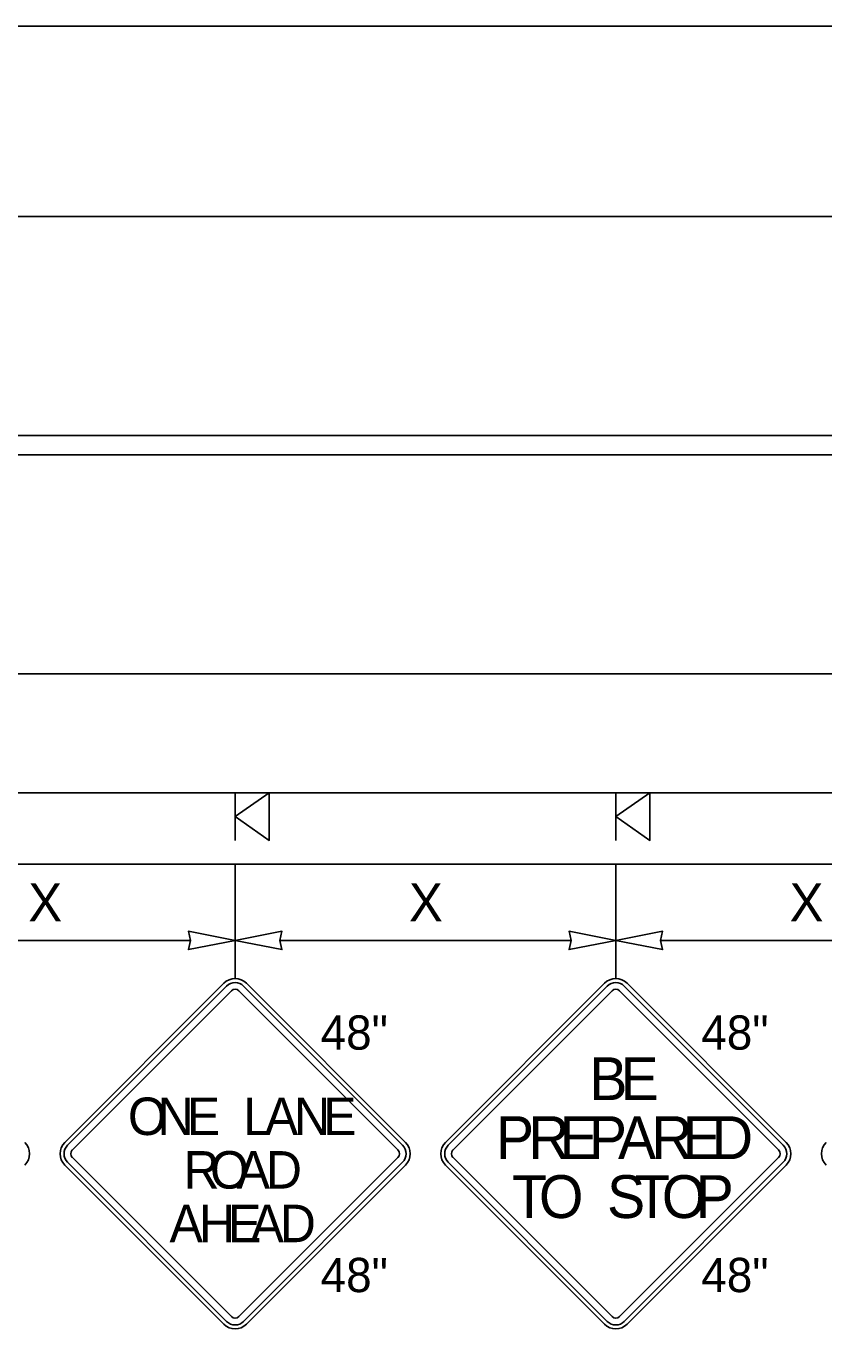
# Model space of a CAD drawing. Extents: x 99999.1 to 100095.7, y 99995 to 100010.7.
# Drawn here: x 100001.437 to 100003.114, y 100004.757 to 100007.492 of the extents above; entities that cross this region are included whole.
import ezdxf

# ---------------------------------------------------------------- set-up
doc = ezdxf.new("R2010")
doc.units = 0
for name, color, linetype in [('RD_ED_ShoulderPavedEdge', 7, 'Continuous'), ('RD_MK_LineDblYellowCenter', 7, 'Continuous'), ('RD_MK_LineEdgeWhite', 7, 'Continuous'), ('TR_SN_ConstructionSigns', 7, 'Continuous'), ('TR_WZ_PortableSignMountBlk-Org', 7, 'Continuous'), ('TR_WZ_WorkZoneDetails', 7, 'Continuous'), ('TR_WZ_WorkZoneTextCurrent', 7, 'Continuous')]:
    doc.layers.add(name, color=color, linetype=linetype)

msp = doc.modelspace()

# ---------------------------------------------------------------- linework, layer by layer
at = {"layer": 'RD_ED_ShoulderPavedEdge'}
for p, q in [((100000.1076, 100007.4923), (100015.6424, 100007.4923)), ((100000.1076, 100005.7323), (100015.6424, 100005.7323))]:
    msp.add_line(p, q, dxfattribs=at)
at = {"layer": 'RD_MK_LineDblYellowCenter'}
for p, q in [((100000.1282, 100006.6323), (100003.4767, 100006.6323)), ((100000.0869, 100006.5923), (100003.4767, 100006.5923))]:
    msp.add_line(p, q, dxfattribs=at)
at = {"layer": 'RD_MK_LineEdgeWhite'}
for p, q in [((100000.1076, 100007.0923), (100015.6424, 100007.0923)), ((100000.1076, 100006.1323), (100015.6424, 100006.1323))]:
    msp.add_line(p, q, dxfattribs=at)
at = {"layer": 'TR_SN_ConstructionSigns'}
for p, q in [((100001.8528, 100005.4824), (100001.5187, 100005.1483)), ((100001.8588, 100005.4765), (100001.5246, 100005.1424)), ((100001.5346, 100005.1324), (100001.8687, 100005.4665)), ((100001.8846, 100005.4665), (100002.2187, 100005.1324)), ((100002.2287, 100005.1424), (100001.8945, 100005.4765)), ((100002.2346, 100005.1483), (100001.9005, 100005.4824)), ((100002.6528, 100005.4824), (100002.3187, 100005.1483)), ((100002.6588, 100005.4765), (100002.3246, 100005.1424)), ((100002.3346, 100005.1324), (100002.6687, 100005.4665)), ((100002.6846, 100005.4665), (100003.0187, 100005.1324)), ((100003.0287, 100005.1424), (100002.6945, 100005.4765)), ((100003.0346, 100005.1483), (100002.7005, 100005.4824)), ((100001.5246, 100005.1066), (100001.8588, 100004.7725)), ((100001.8687, 100004.7824), (100001.5346, 100005.1165)), ((100002.2187, 100005.1165), (100001.8846, 100004.7824)), ((100001.8945, 100004.7725), (100002.2287, 100005.1066)), ((100002.3246, 100005.1066), (100002.6588, 100004.7725)), ((100002.6687, 100004.7824), (100002.3346, 100005.1165)), ((100003.0187, 100005.1165), (100002.6846, 100004.7824)), ((100002.6945, 100004.7725), (100003.0287, 100005.1066)), ((100001.5187, 100005.1006), (100001.8528, 100004.7665)), ((100001.9005, 100004.7665), (100002.2346, 100005.1006)), ((100002.3187, 100005.1006), (100002.6528, 100004.7665)), ((100002.7005, 100004.7665), (100003.0346, 100005.1006))]:
    msp.add_line(p, q, dxfattribs=at)
for centre, radius, start, end in [((100001.8767, 100005.4586), 0.0338, 45, 135), ((100002.6767, 100005.4586), 0.0338, 45, 135), ((100001.8767, 100005.4586), 0.0253, 45, 135), ((100001.8767, 100005.4586), 0.0113, 45, 135), ((100002.6767, 100005.4586), 0.0253, 45, 135), ((100002.6767, 100005.4586), 0.0113, 45, 135), ((100001.4108, 100005.1245), 0.0338, 315, 45), ((100001.5425, 100005.1245), 0.0338, 135, 225), ((100001.5425, 100005.1245), 0.0253, 135, 225), ((100002.2108, 100005.1245), 0.0253, 315, 45), ((100002.2108, 100005.1245), 0.0338, 315, 45), ((100002.3425, 100005.1245), 0.0338, 135, 225), ((100002.3425, 100005.1245), 0.0253, 135, 225), ((100003.0108, 100005.1245), 0.0253, 315, 45), ((100003.0108, 100005.1245), 0.0338, 315, 45), ((100003.1425, 100005.1245), 0.0338, 135, 225), ((100001.5425, 100005.1245), 0.0113, 135, 225), ((100002.2108, 100005.1245), 0.0113, 315, 45), ((100002.3425, 100005.1245), 0.0113, 135, 225), ((100003.0108, 100005.1245), 0.0113, 315, 45), ((100001.8767, 100004.7904), 0.0113, 225, 315), ((100002.6767, 100004.7904), 0.0113, 225, 315), ((100001.8767, 100004.7904), 0.0338, 225, 315), ((100001.8767, 100004.7904), 0.0253, 225, 315), ((100002.6767, 100004.7904), 0.0338, 225, 315), ((100002.6767, 100004.7904), 0.0253, 225, 315)]:
    msp.add_arc(centre, radius, start, end, dxfattribs=at)
at = {"layer": 'TR_WZ_PortableSignMountBlk-Org'}
for p, q in [((100001.8767, 100005.7824), (100001.8767, 100005.8824)), ((100002.6767, 100005.7824), (100002.6767, 100005.8824))]:
    msp.add_line(p, q, dxfattribs=at)
for points in [[(100001.8767, 100005.8323), (100001.9485, 100005.8824), (100001.9485, 100005.7824)], [(100002.6767, 100005.8323), (100002.7485, 100005.8824), (100002.7485, 100005.7824)]]:
    msp.add_lwpolyline(points, close=True, dxfattribs=at)
at = {"layer": 'TR_WZ_WorkZoneDetails'}
for p, q in [((100001.0767, 100005.8824), (100003.4767, 100005.8824)), ((100001.8767, 100005.7323), (100001.8767, 100005.4923)), ((100002.6767, 100005.7323), (100002.6767, 100005.4923)), ((100001.7829, 100005.5723), (100001.1704, 100005.5723)), ((100002.5829, 100005.5723), (100001.9704, 100005.5723)), ((100003.3829, 100005.5723), (100002.7704, 100005.5723))]:
    msp.add_line(p, q, dxfattribs=at)
for points in [[(100001.8767, 100005.5723), (100001.7784, 100005.5916), (100001.7829, 100005.5723), (100001.7784, 100005.5531)], [(100001.8767, 100005.5723), (100001.9749, 100005.5916), (100001.9704, 100005.5723), (100001.9749, 100005.5531)], [(100002.6767, 100005.5723), (100002.5784, 100005.5916), (100002.5829, 100005.5723), (100002.5784, 100005.5531)], [(100002.6767, 100005.5723), (100002.7749, 100005.5916), (100002.7704, 100005.5723), (100002.7749, 100005.5531)]]:
    msp.add_lwpolyline(points, close=True, dxfattribs=at)

# ---------------------------------------------------------------- texts
at = {"layer": 'TR_SN_ConstructionSigns'}
for p in [(100002.0564, 100005.343), (100002.8564, 100005.343), (100002.0564, 100004.8339), (100002.8564, 100004.8339)]:
    msp.add_text('48"', height=0.072, rotation=360, dxfattribs=at).set_placement(p)
for s, height, p in [('B', 0.09, (100002.6209, 100005.237)), ('E', 0.09, (100002.6866, 100005.237)), ('O', 0.0787, (100001.6514, 100005.1638)), ('N', 0.0787, (100001.7136, 100005.1638)), ('E', 0.0787, (100001.7751, 100005.1638)), ('L', 0.0787, (100001.894, 100005.1638)), ('A', 0.0787, (100001.9389, 100005.1638)), ('N', 0.0787, (100002.0003, 100005.1638)), ('E', 0.0787, (100002.0617, 100005.1638)), ('P', 0.09, (100002.4247, 100005.1132)), ('R', 0.09, (100002.4931, 100005.1132)), ('E', 0.09, (100002.5588, 100005.1132)), ('P', 0.09, (100002.62, 100005.1132)), ('A', 0.09, (100002.6812, 100005.1132)), ('R', 0.09, (100002.7514, 100005.1132)), ('E', 0.09, (100002.8171, 100005.1132)), ('D', 0.09, (100002.8783, 100005.1132)), ('R', 0.0787, (100001.768, 100005.0513)), ('O', 0.0787, (100001.8239, 100005.0513)), ('A', 0.0787, (100001.8798, 100005.0513)), ('D', 0.0787, (100001.9412, 100005.0513)), ('T', 0.09, (100002.4584, 100004.9895)), ('O', 0.09, (100002.5151, 100004.9895)), ('S', 0.09, (100002.6582, 100004.9895)), ('T', 0.09, (100002.7167, 100004.9895)), ('O', 0.09, (100002.7734, 100004.9895)), ('P', 0.09, (100002.8445, 100004.9895)), ('A', 0.0787, (100001.7388, 100004.9388)), ('H', 0.0787, (100001.8003, 100004.9388)), ('E', 0.0787, (100001.8617, 100004.9388)), ('A', 0.0787, (100001.9089, 100004.9388)), ('D', 0.0787, (100001.9704, 100004.9388))]:
    msp.add_text(s, height=height, dxfattribs=at).set_placement(p)
at = {"layer": 'TR_WZ_WorkZoneTextCurrent'}
for p in [(100001.4419, 100005.6123), (100002.2419, 100005.6123), (100003.0419, 100005.6123)]:
    msp.add_text('X', height=0.08, rotation=360, dxfattribs=at).set_placement(p)

doc.saveas('drawing.dxf')
